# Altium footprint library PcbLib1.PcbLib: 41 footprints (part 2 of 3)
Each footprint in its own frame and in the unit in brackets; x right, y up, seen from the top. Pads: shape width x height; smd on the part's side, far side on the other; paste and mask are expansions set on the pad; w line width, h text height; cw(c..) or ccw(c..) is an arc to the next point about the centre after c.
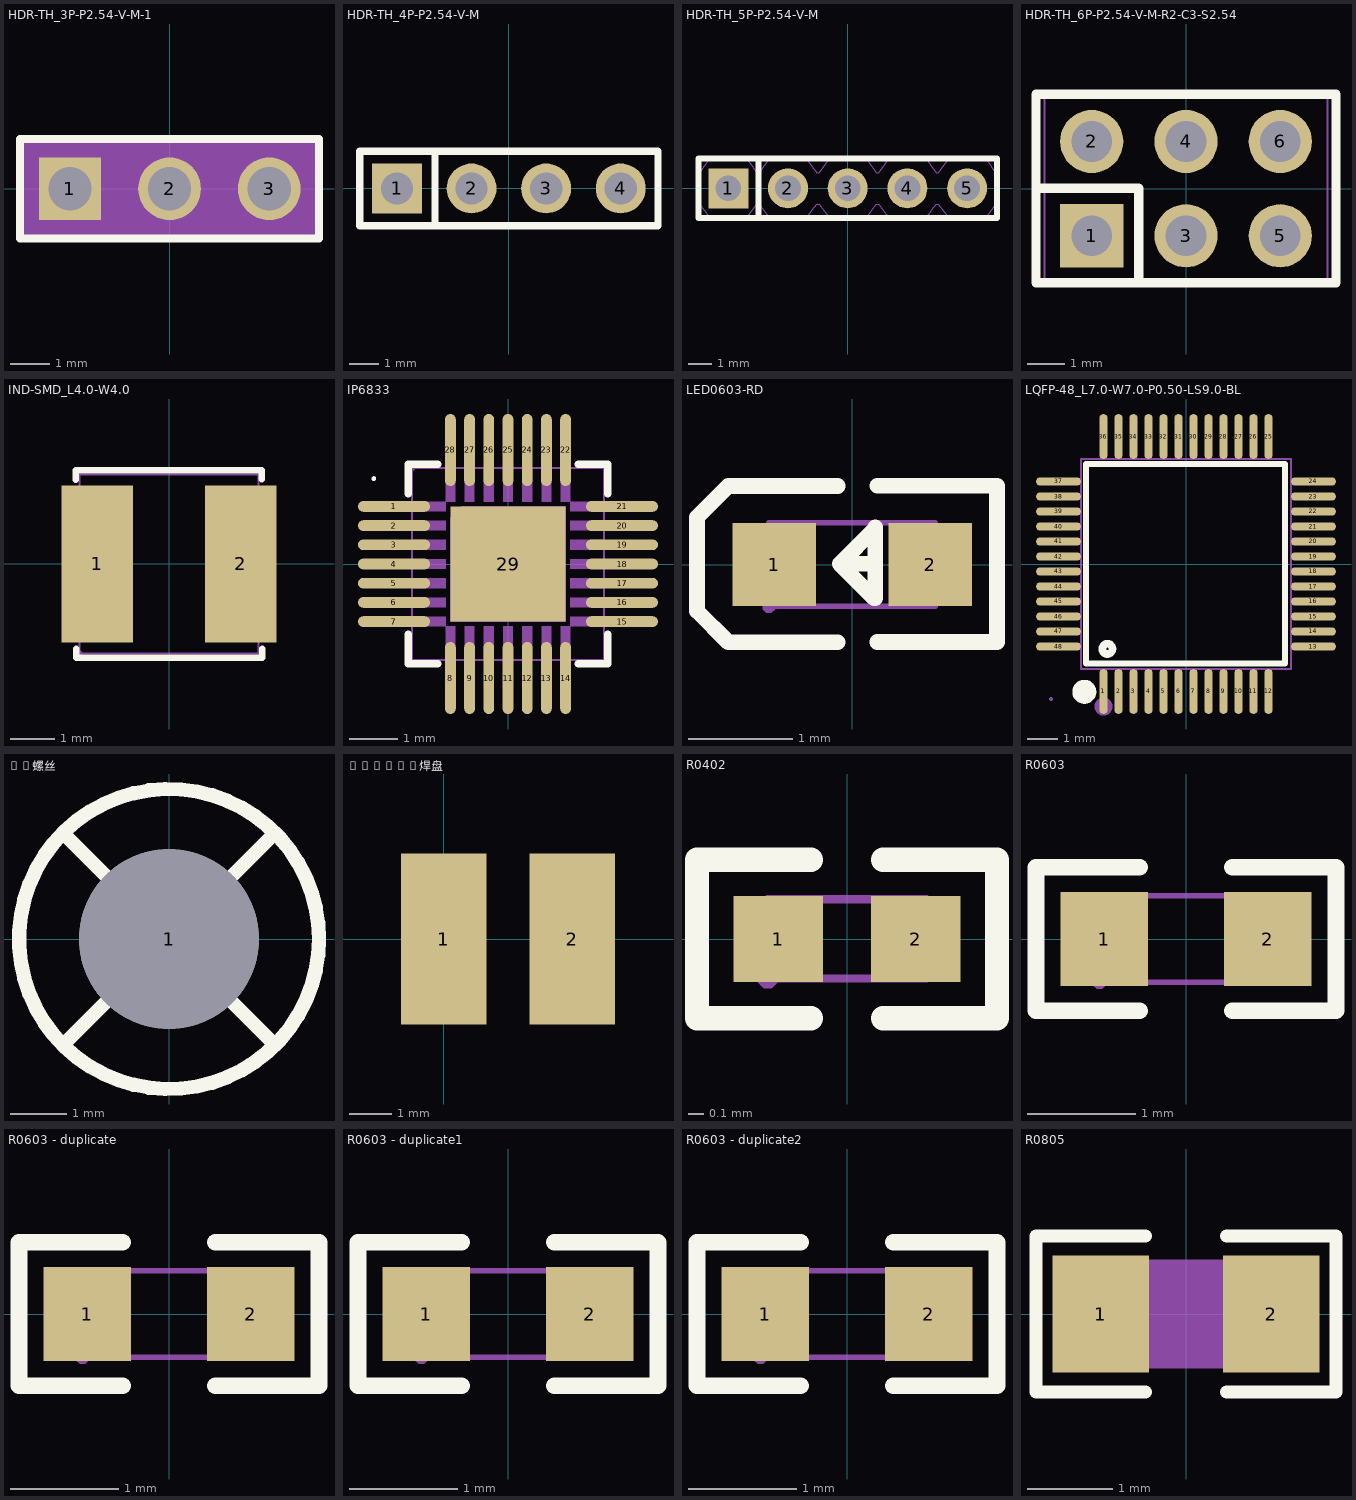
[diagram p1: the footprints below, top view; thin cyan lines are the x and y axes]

## HDR-TH_3P-P2.54-V-M-1 [mm]
pads (3):
  rect 1.575x1.6 hole 1.1 paste-2539.97 mask+0.05: 1(-2.54,0)
  round 1.6 hole 1.1 paste-2539.97 mask+0.05: 2(0,0) 3(2.54,0)
Top Overlay:
  lines w0.203: -3.81,-1.27 -3.81,1.27 -1.905,1.27 3.81,1.27 3.81,-1.27 -3.81,-1.27
Mechanical 9:
  region: -3.81,-1.25 -3.81,1.25 3.81,1.25 3.81,-1.25
Mechanical 11:
  region: -3.78,-1.25 -3.78,-1.262 -3.798,-1.28 -3.822,-1.28 -3.84,-1.262 -3.84,-1.25 -3.84,-1.238 -3.822,-1.22 -3.798,-1.22 -3.78,-1.238 -3.78,-1.25
Mechanical 12:
  region: 2.22,0.32 2.86,0.32 2.86,-0.32 2.22,-0.32
  region: -0.32,0.32 0.32,0.32 0.32,-0.32 -0.32,-0.32
  region: -2.86,0.32 -2.22,0.32 -2.22,-0.32 -2.86,-0.32

## HDR-TH_4P-P2.54-V-M [mm]
pads (4):
  rect 1.7x1.7 hole 1.1: 1(-3.81,0)
  round 1.7 hole 1.1: 2(-1.27,0) 3(1.27,0) 4(3.81,0)
Top Overlay:
  lines w0.254: -2.516,-1.27 -2.516,1.27 ; -2.516,1.27 -5.08,1.27 -5.08,-1.27 5.08,-1.27 5.08,1.27 -2.516,1.27
Mechanical 6:
  lines w0.051: -5.08,-1.25 5.08,-1.25 5.08,1.25 -5.08,1.25 -5.08,-1.25
Mechanical 8:
  region: -5.02,-1.25 -5.02,-1.275 -5.055,-1.31 -5.105,-1.31 -5.14,-1.275 -5.14,-1.25 -5.14,-1.225 -5.105,-1.19 -5.055,-1.19 -5.02,-1.225 -5.02,-1.25
Mechanical 9:
  region: 3.49,0.32 4.13,0.32 4.13,-0.32 3.49,-0.32
  region: 0.95,0.32 1.59,0.32 1.59,-0.32 0.95,-0.32
  region: -1.59,0.32 -0.95,0.32 -0.95,-0.32 -1.59,-0.32
  region: -4.13,0.32 -3.49,0.32 -3.49,-0.32 -4.13,-0.32

## HDR-TH_5P-P2.54-V-M [mm]
pads (5):
  rect 1.7x1.7 hole 1.1: 1(-5.08,0)
  round 1.7 hole 1.1: 2(-2.54,0) 3(0,0) 4(2.54,0) 5(5.08,0)
Top Overlay:
  lines w0.254: -3.786,-1.27 -3.786,1.27 ; -6.35,-1.27 -6.35,1.27 6.35,1.27 6.35,-1.27 -6.35,-1.27
Mechanical 6:
  lines w0.051: -6.35,-0.67 -6.35,-0.67 -6.3,-0.67 -5.85,-1.27 -4.31,-1.27 -4.077,-0.965 -3.86,-0.67 -3.76,-0.67 -3.31,-1.27 -1.77,-1.27 -1.542,-0.972 -1.503,-0.919 -1.32,-0.67 -1.22,-0.67 -0.77,-1.27 0.77,-1.27 0.992,-0.98 1.02,-0.942 1.22,-0.67 1.32,-0.67 1.77,-1.27 3.31,-1.271 3.51,-1.009 3.545,-0.963 3.581,-0.913 3.759,-0.67 3.86,-0.67 4.31,-1.27 5.85,-1.27 6.075,-0.976 6.3,-0.67 6.35,-0.67 6.35,0.67 6.3,0.67 6.112,0.925 6.079,0.97 5.85,1.27 4.311,1.27 3.86,0.67 3.76,0.67 3.533,0.979 3.458,1.076 3.31,1.27 1.77,1.27 1.32,0.67 1.22,0.67 1.136,0.783 1.108,0.822 1.01,0.955 0.867,1.143 0.77,1.27 -0.77,1.27 -1.22,0.67 -1.32,0.67 -1.417,0.801 -1.436,0.827 -1.459,0.859 -1.546,0.976 -1.631,1.088 -1.77,1.27 -3.31,1.27 -3.76,0.67 -3.86,0.67 -4.017,0.884 -4.048,0.925 -4.149,1.059 -4.31,1.27 -5.85,1.27 -6.028,1.032 -6.299,0.67 -6.35,0.67 -6.35,-0.67 ; -6.35,-0.67 -6.35,-0.67
Mechanical 8:
  region: -6.29,-1.271 -6.29,-1.296 -6.325,-1.331 -6.375,-1.331 -6.41,-1.296 -6.41,-1.271 -6.41,-1.246 -6.375,-1.211 -6.325,-1.211 -6.29,-1.246 -6.29,-1.271
Mechanical 9:
  region: -5.4,0.32 -4.76,0.32 -4.76,-0.32 -5.4,-0.32
  region: -2.86,0.32 -2.22,0.32 -2.22,-0.32 -2.86,-0.32
  region: -0.32,0.32 0.32,0.32 0.32,-0.32 -0.32,-0.32
  region: 2.22,0.32 2.86,0.32 2.86,-0.32 2.22,-0.32
  region: 4.76,0.32 5.4,0.32 5.4,-0.32 4.76,-0.32

## HDR-TH_6P-P2.54-V-M-R2-C3-S2.54 [mm]
pads (6):
  rect 1.7x1.7 hole 1.1: 1(-2.54,-1.27)
  round 1.7 hole 1.1: 2(-2.54,1.27) 3(0,-1.27) 4(0,1.27) 5(2.54,-1.27) 6(2.54,1.27)
Top Overlay:
  lines w0.254: -4.04,0.007 -1.27,0.007 -1.27,-2.54 ; -4.04,-2.54 -4.04,2.54 4.04,2.54 4.04,-2.54 -4.04,-2.54
Mechanical 6:
  lines w0.051: -3.81,-2.5 3.81,-2.5 3.81,2.5 -3.81,2.5 -3.81,-2.5
Mechanical 8:
  region: -3.75,-2.5 -3.75,-2.525 -3.785,-2.56 -3.835,-2.56 -3.87,-2.525 -3.87,-2.5 -3.87,-2.475 -3.835,-2.44 -3.785,-2.44 -3.75,-2.475 -3.75,-2.5
Mechanical 9:
  region: -2.86,-0.95 -2.22,-0.95 -2.22,-1.59 -2.86,-1.59
  region: -2.86,1.59 -2.22,1.59 -2.22,0.95 -2.86,0.95
  region: -0.32,-0.95 0.32,-0.95 0.32,-1.59 -0.32,-1.59
  region: -0.32,1.59 0.32,1.59 0.32,0.95 -0.32,0.95
  region: 2.22,-0.95 2.86,-0.95 2.86,-1.59 2.22,-1.59
  region: 2.22,1.59 2.86,1.59 2.86,0.95 2.22,0.95

## IND-SMD_L4.0-W4.0 [mm]
pads (2):
  rect 1.6x3.5 smd: 1(-1.6,0) 2(1.6,0)
Top Overlay:
  lines w0.15: -2.08,1.88 -2.083,2.095 2.07,2.095 2.07,1.9 ; -2.07,-1.89 -2.07,-2.096 2.082,-2.096 2.08,-1.9
Mechanical 6:
  lines w0.051: -2,-2 2,-2 2,2 -2,2 -2,-2
Mechanical 8:
  region: -1.94,-2 -1.94,-2.025 -1.975,-2.06 -2.025,-2.06 -2.06,-2.025 -2.06,-2 -2.06,-1.975 -2.025,-1.94 -1.975,-1.94 -1.94,-1.975 -1.94,-2
Mechanical 9:
  region: -2,1.65 -1.05,1.65 -1.05,-1.65 -2,-1.65
  region: 1.05,1.65 2,1.65 2,-1.65 1.05,-1.65

## IP6833 [mil]
pads (29):
  oval 59x8.82 smd paste+0 mask+2: 1(-93.49,47.24) 2(-93.5,31.5) 3(-93.5,15.75) 4(-93.5,0) 5(-93.5,-15.75) 6(-93.5,-31.5) 7(-93.5,-47.24)
  oval 8.82x59 smd paste+0 mask+2: 8(-47.24,-93.5)
  oval 8.82x59 smd paste-99999 mask+2: 9(-31.5,-93.5) 10(-15.75,-93.5) 11(0,-93.5) 12(15.75,-93.5) 13(31.5,-93.5) 14(47.24,-93.5) 22(47.24,93.5) 23(31.5,93.5) 24(15.75,93.5) 25(0,93.5) 26(-15.75,93.5) 27(-31.5,93.5) 28(-47.24,93.5)
  oval 59x8.82 smd paste-99999 mask+2: 15(93.5,-47.24) 16(93.5,-31.5) 17(93.5,-15.75) 18(93.5,0) 19(93.5,15.75) 20(93.5,31.5) 21(93.49,47.24)
  rect 94.49x94.49 smd paste-99999 mask+2: 29(0,0)
Top Overlay:
  circle w1.97: c-110,70 r0.98
  lines w6: -81.74,-57.65 -81.74,-81.74 -57.65,-81.74 ; -81.74,57.65 -81.74,81.74 -57.65,81.74 ; 57.65,-81.74 81.74,-81.74 81.74,-57.65 ; 57.65,81.74 81.74,81.74 81.74,57.65
Mechanical 6:
  circle w1.97: c-105.15,47.24 r0.98
Mechanical 7:
  lines w2: -78.74,-78.74 78.74,-78.74 78.74,78.74 -78.74,78.74 -78.74,-78.74
Mechanical 8:
  region: -76.38,78.74 -76.38,77.76 -77.76,76.38 -79.72,76.38 -81.1,77.76 -81.1,78.74 -81.1,79.72 -79.72,81.1 -77.76,81.1 -76.38,79.72 -76.38,78.74
Mechanical 9:
  region: -78.74,43.31 -51.18,43.31 -51.18,51.18 -78.74,51.18
  region: -78.74,27.56 -51.18,27.56 -51.18,35.43 -78.74,35.43
  region: -78.74,11.81 -51.18,11.81 -51.18,19.68 -78.74,19.68
  region: -78.74,-3.94 -51.18,-3.94 -51.18,3.94 -78.74,3.94
  region: -78.74,-19.68 -51.18,-19.68 -51.18,-11.81 -78.74,-11.81
  region: -78.74,-35.43 -51.18,-35.43 -51.18,-27.56 -78.74,-27.56
  region: -78.74,-51.18 -51.18,-51.18 -51.18,-43.31 -78.74,-43.31
  region: -51.18,-78.74 -43.31,-78.74 -43.31,-51.18 -51.18,-51.18
  region: -35.43,-78.74 -27.56,-78.74 -27.56,-51.18 -35.43,-51.18
  region: -19.68,-78.74 -11.81,-78.74 -11.81,-51.18 -19.68,-51.18
  region: -3.94,-78.74 3.94,-78.74 3.94,-51.18 -3.94,-51.18
  region: 11.81,-78.74 19.68,-78.74 19.68,-51.18 11.81,-51.18
  region: 27.56,-78.74 35.43,-78.74 35.43,-51.18 27.56,-51.18
  region: 43.31,-78.74 51.18,-78.74 51.18,-51.18 43.31,-51.18
  region: 78.74,-51.18 51.18,-51.18 51.18,-43.31 78.74,-43.31
  region: 78.74,-35.43 51.18,-35.43 51.18,-27.56 78.74,-27.56
  region: 78.74,-19.68 51.18,-19.68 51.18,-11.81 78.74,-11.81
  region: 78.74,-3.94 51.18,-3.94 51.18,3.94 78.74,3.94
  region: 78.74,11.81 51.18,11.81 51.18,19.68 78.74,19.68
  region: 78.74,27.56 51.18,27.56 51.18,35.43 78.74,35.43
  region: 78.74,43.31 51.18,43.31 51.18,51.18 78.74,51.18
  region: 43.31,78.74 51.18,78.74 51.18,51.18 43.31,51.18
  region: 27.56,78.74 35.43,78.74 35.43,51.18 27.56,51.18
  region: 11.81,78.74 19.68,78.74 19.68,51.18 11.81,51.18
  region: -3.94,78.74 3.94,78.74 3.94,51.18 -3.94,51.18
  region: -19.68,78.74 -11.81,78.74 -11.81,51.18 -19.68,51.18
  region: -35.43,78.74 -27.56,78.74 -27.56,51.18 -35.43,51.18
  region: -51.18,78.74 -43.31,78.74 -43.31,51.18 -51.18,51.18
  region: -37.8,47.24 47.24,47.24 47.24,-47.24 -47.24,-47.24 -47.24,37.8

## LED0603-RD [mm]
pads (2):
  rect 0.8x0.8 smd: 1(-0.749,0) 2(0.749,0)
Top Overlay:
  lines w0.15: -0.14,-0.746 -1.19,-0.746 -1.49,-0.446 -1.49,-0.346 -1.49,0.354 -1.49,0.454 -1.19,0.754 -0.14,0.754 ; 0.22,0.007 -0.12,0.007 ; 0.24,-0.744 1.39,-0.744 ; 0.24,0.757 1.39,0.757 1.39,-0.723 ; -0.12,0.007 0.22,0.347 0.22,0.357 0.22,-0.324 0.21,-0.324 -0.12,0.007
Mechanical 2:
  region: 0.529,0.068 1.069,0.068 1.069,-0.062 0.529,-0.062
  region: 0.735,-0.267 0.735,0.273 0.865,0.273 0.865,-0.267
  region: -1.07,0.062 -0.53,0.062 -0.53,-0.068 -1.07,-0.068
Mechanical 6:
  lines w0.051: -0.8,-0.4 0.8,-0.4 0.8,0.4 -0.8,0.4 -0.8,-0.4
Mechanical 8:
  region: -0.739,-0.403 -0.739,-0.428 -0.775,-0.463 -0.824,-0.463 -0.859,-0.428 -0.859,-0.403 -0.859,-0.379 -0.824,-0.344 -0.775,-0.344 -0.739,-0.379 -0.739,-0.403
Mechanical 9:
  region: 0.5,-0.396 0.5,0.404 0.8,0.404 0.8,-0.396
  region: -0.8,-0.403 -0.8,0.397 -0.5,0.397 -0.5,-0.403

## LQFP-48_L7.0-W7.0-P0.50-LS9.0-BL [mm]
pads (48):
  oval 0.27x1.5 smd paste+0 mask+0.05: 1(-2.75,-4.25) 2(-2.25,-4.25) 3(-1.75,-4.25) 4(-1.25,-4.25) 5(-0.75,-4.25) 6(-0.25,-4.25) 7(0.25,-4.25) 8(0.75,-4.25) 9(1.25,-4.25) 10(1.75,-4.25) 11(2.25,-4.25) 12(2.75,-4.25) 25(2.75,4.25) 26(2.25,4.25) 27(1.75,4.25) 28(1.25,4.25) 29(0.75,4.25) 30(0.25,4.25) 31(-0.25,4.25) 32(-0.75,4.25) 33(-1.25,4.25) 34(-1.75,4.25) 35(-2.25,4.25) 36(-2.75,4.25)
  oval 1.5x0.27 smd paste+0 mask+0.05: 13(4.25,-2.75) 14(4.25,-2.25) 15(4.25,-1.75) 16(4.25,-1.25) 17(4.25,-0.75) 18(4.25,-0.25) 19(4.25,0.25) 20(4.25,0.75) 21(4.25,1.25) 22(4.25,1.75) 23(4.25,2.25) 24(4.25,2.75) 37(-4.25,2.75) 38(-4.25,2.25) 39(-4.25,1.75) 40(-4.25,1.25) 41(-4.25,0.75) 42(-4.25,0.25) 43(-4.25,-0.25) 44(-4.25,-0.75) 45(-4.25,-1.25) 46(-4.25,-1.75) 47(-4.25,-2.25) 48(-4.25,-2.75)
Top Overlay:
  circle w0.254: c-2.62,-2.83 r0.17
  lines w0.2: -2.896,3.34 3.302,3.34 3.302,-3.315 -3.327,-3.315 -3.327,3.34 -2.565,3.34
  lines w0.4: -3.39,-4.06 ccw(c-3.389,-4.26) -3.387,-4.06
Mechanical 2:
  circle w0.3: c-2.75,-4.75 r0.15
Mechanical 6:
  lines w0.051: -3.5,-3.5 -3.5,3.5 3.5,3.5 3.5,-3.5 -3.5,-3.5
Mechanical 7:
  drawing of 48 lines, arcs and shapes, not listed
Mechanical 8:
  region: -4.44,-4.5 -4.44,-4.525 -4.475,-4.56 -4.525,-4.56 -4.56,-4.525 -4.56,-4.5 -4.56,-4.475 -4.525,-4.44 -4.475,-4.44 -4.44,-4.475 -4.44,-4.5
Mechanical 9:
  drawing of 48 lines, arcs and shapes, not listed

## M3螺丝 [mil]
pads (1):
  round 126 hole 126 paste-99999 mask+4: 1(0,0)
Top Overlay:
  circle w10: c0,0 r105
  lines w10: -72.5,-72.5 72.5,72.5 ; -72.5,72.5 72.5,-72.5

## PT1000焊盘 [mm]
pads (2):
  rect 2x4 smd: 1(0,0) 2(3,0)

## R0402 [mm]
pads (2):
  rect 0.566x0.54 smd paste-100 mask+0.051: 1(-0.433,0) 2(0.433,0)
Top Overlay:
  lines w0.152: -0.226,-0.499 -0.944,-0.499 -0.944,0.499 -0.226,0.499 ; 0.226,-0.499 0.944,-0.499 0.944,0.499 0.226,0.499
Top Paste:
  region: -0.135,-0.23 -0.135,0.23 -0.175,0.27 -0.676,0.27 -0.716,0.23 -0.716,-0.23 -0.676,-0.27 -0.175,-0.27
  region: 0.135,-0.23 0.135,0.23 0.175,0.27 0.676,0.27 0.716,0.23 0.716,-0.23 0.676,-0.27 0.175,-0.27
Mechanical 6:
  lines w0.051: -0.5,-0.25 0.5,-0.25 0.5,0.25 -0.5,0.25 -0.5,-0.25
Mechanical 8:
  region: -0.44,-0.25 -0.44,-0.275 -0.475,-0.31 -0.525,-0.31 -0.56,-0.275 -0.56,-0.25 -0.56,-0.225 -0.525,-0.19 -0.475,-0.19 -0.44,-0.225 -0.44,-0.25
Mechanical 9:
  region: -0.249,0.25 -0.249,-0.25 -0.499,-0.25 -0.499,0.25
  region: 0.251,-0.25 0.251,0.25 0.501,0.25 0.501,-0.25

## R0603 [mm]
pads (2):
  rect 0.806x0.864 smd paste-100 mask+0.051: 1(-0.753,0) 2(0.753,0)
Top Overlay:
  lines w0.152: -0.426,-0.661 -1.385,-0.661 -1.385,0.661 -0.426,0.661 ; 0.426,-0.661 1.385,-0.661 1.385,0.661 0.426,0.661
Top Paste:
  region: 1.195,0.45 0.395,0.45 0.345,0.4 0.345,0.172 0.715,0.172 0.715,-0.158 0.345,-0.158 0.345,-0.4 0.395,-0.45 1.195,-0.45 1.245,-0.4 1.245,0.4
  region: -1.195,-0.45 -0.395,-0.45 -0.345,-0.4 -0.345,-0.172 -0.715,-0.172 -0.715,0.158 -0.345,0.158 -0.345,0.4 -0.395,0.45 -1.195,0.45 -1.245,0.4 -1.245,-0.4
Mechanical 6:
  lines w0.051: -0.8,-0.4 -0.8,0.4 0.8,0.4 0.8,-0.4 -0.8,-0.4
Mechanical 8:
  region: -0.74,-0.4 -0.74,-0.425 -0.775,-0.46 -0.825,-0.46 -0.86,-0.425 -0.86,-0.4 -0.86,-0.375 -0.825,-0.34 -0.775,-0.34 -0.74,-0.375 -0.74,-0.4
Mechanical 9:
  region: -0.8,-0.4 -0.8,0.4 -0.5,0.4 -0.5,-0.4
  region: 0.8,-0.4 0.8,0.4 0.5,0.4 0.5,-0.4

## R0603 - duplicate [mm]
pads (2):
  rect 0.806x0.864 smd paste-100 mask+0.051: 1(-0.753,0) 2(0.753,0)
Top Overlay:
  lines w0.152: -0.426,-0.661 -1.385,-0.661 -1.385,0.661 -0.426,0.661 ; 0.426,-0.661 1.385,-0.661 1.385,0.661 0.426,0.661
Top Paste:
  region: 1.195,0.45 0.395,0.45 0.345,0.4 0.345,0.172 0.715,0.172 0.715,-0.158 0.345,-0.158 0.345,-0.4 0.395,-0.45 1.195,-0.45 1.245,-0.4 1.245,0.4
  region: -1.195,-0.45 -0.395,-0.45 -0.345,-0.4 -0.345,-0.172 -0.715,-0.172 -0.715,0.158 -0.345,0.158 -0.345,0.4 -0.395,0.45 -1.195,0.45 -1.245,0.4 -1.245,-0.4
Mechanical 6:
  lines w0.051: -0.8,-0.4 -0.8,0.4 0.8,0.4 0.8,-0.4 -0.8,-0.4
Mechanical 8:
  region: -0.74,-0.4 -0.74,-0.425 -0.775,-0.46 -0.825,-0.46 -0.86,-0.425 -0.86,-0.4 -0.86,-0.375 -0.825,-0.34 -0.775,-0.34 -0.74,-0.375 -0.74,-0.4
Mechanical 9:
  region: -0.8,-0.4 -0.8,0.4 -0.5,0.4 -0.5,-0.4
  region: 0.8,-0.4 0.8,0.4 0.5,0.4 0.5,-0.4

## R0603 - duplicate1 [mm]
pads (2):
  rect 0.806x0.864 smd paste-100 mask+0.051: 1(-0.753,0) 2(0.753,0)
Top Overlay:
  lines w0.152: -0.426,-0.661 -1.385,-0.661 -1.385,0.661 -0.426,0.661 ; 0.426,-0.661 1.385,-0.661 1.385,0.661 0.426,0.661
Top Paste:
  region: -1.195,-0.45 -0.395,-0.45 -0.345,-0.4 -0.345,-0.172 -0.715,-0.172 -0.715,0.158 -0.345,0.158 -0.345,0.4 -0.395,0.45 -1.195,0.45 -1.245,0.4 -1.245,-0.4
  region: 1.195,0.45 0.395,0.45 0.345,0.4 0.345,0.172 0.715,0.172 0.715,-0.158 0.345,-0.158 0.345,-0.4 0.395,-0.45 1.195,-0.45 1.245,-0.4 1.245,0.4
Mechanical 6:
  lines w0.051: -0.8,-0.4 0.8,-0.4 0.8,0.4 -0.8,0.4 -0.8,-0.4
Mechanical 8:
  region: -0.74,-0.4 -0.74,-0.425 -0.775,-0.46 -0.825,-0.46 -0.86,-0.425 -0.86,-0.4 -0.86,-0.375 -0.825,-0.34 -0.775,-0.34 -0.74,-0.375 -0.74,-0.4
Mechanical 9:
  region: 0.8,-0.4 0.8,0.4 0.5,0.4 0.5,-0.4
  region: -0.8,-0.4 -0.8,0.4 -0.5,0.4 -0.5,-0.4

## R0603 - duplicate2 [mm]
pads (2):
  rect 0.806x0.864 smd paste-100 mask+0.051: 1(-0.753,0) 2(0.753,0)
Top Overlay:
  lines w0.152: -0.426,-0.661 -1.385,-0.661 -1.385,0.661 -0.426,0.661 ; 0.426,-0.661 1.385,-0.661 1.385,0.661 0.426,0.661
Top Paste:
  region: 1.195,0.45 0.395,0.45 0.345,0.4 0.345,0.172 0.715,0.172 0.715,-0.158 0.345,-0.158 0.345,-0.4 0.395,-0.45 1.195,-0.45 1.245,-0.4 1.245,0.4
  region: -1.195,-0.45 -0.395,-0.45 -0.345,-0.4 -0.345,-0.172 -0.715,-0.172 -0.715,0.158 -0.345,0.158 -0.345,0.4 -0.395,0.45 -1.195,0.45 -1.245,0.4 -1.245,-0.4
Mechanical 6:
  lines w0.051: -0.8,-0.4 -0.8,0.4 0.8,0.4 0.8,-0.4 -0.8,-0.4
Mechanical 8:
  region: -0.74,-0.4 -0.74,-0.425 -0.775,-0.46 -0.825,-0.46 -0.86,-0.425 -0.86,-0.4 -0.86,-0.375 -0.825,-0.34 -0.775,-0.34 -0.74,-0.375 -0.74,-0.4
Mechanical 9:
  region: -0.8,-0.4 -0.8,0.4 -0.5,0.4 -0.5,-0.4
  region: 0.8,-0.4 0.8,0.4 0.5,0.4 0.5,-0.4

## R0805 [mm]
pads (2):
  rect 1.133x1.377 smd paste-100 mask+0.051: 1(-1,0) 2(1,0)
Top Overlay:
  lines w0.152: -0.476,-0.917 -1.761,-0.917 -1.761,0.917 -0.476,0.917 ; 0.476,-0.917 1.761,-0.917 1.761,0.917 0.476,0.917
Top Paste:
  region: -1.7,-0.64 -1.7,0.64 -1.65,0.69 -0.5,0.69 -0.45,0.64 -0.445,0.23 -0.895,0.23 -0.895,-0.22 -0.455,-0.22 -0.45,-0.64 -0.5,-0.69 -1.65,-0.69
  region: 0.45,-0.64 0.45,-0.22 0.895,-0.22 0.895,0.23 0.455,0.23 0.45,0.64 0.5,0.69 1.65,0.69 1.7,0.64 1.7,-0.64 1.65,-0.69 0.5,-0.69
Mechanical 9:
  region: -1,-0.637 -1,0.637 1,0.637 1,-0.637
Mechanical 11:
  region: -0.97,-0.638 -0.97,-0.65 -0.988,-0.668 -1.012,-0.668 -1.03,-0.65 -1.03,-0.638 -1.03,-0.625 -1.012,-0.608 -0.988,-0.608 -0.97,-0.625 -0.97,-0.638
Mechanical 12:
  region: -1,-0.637 -1,0.637 -0.6,0.637 -0.6,-0.637
  region: 1,-0.637 1,0.637 0.6,0.637 0.6,-0.637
